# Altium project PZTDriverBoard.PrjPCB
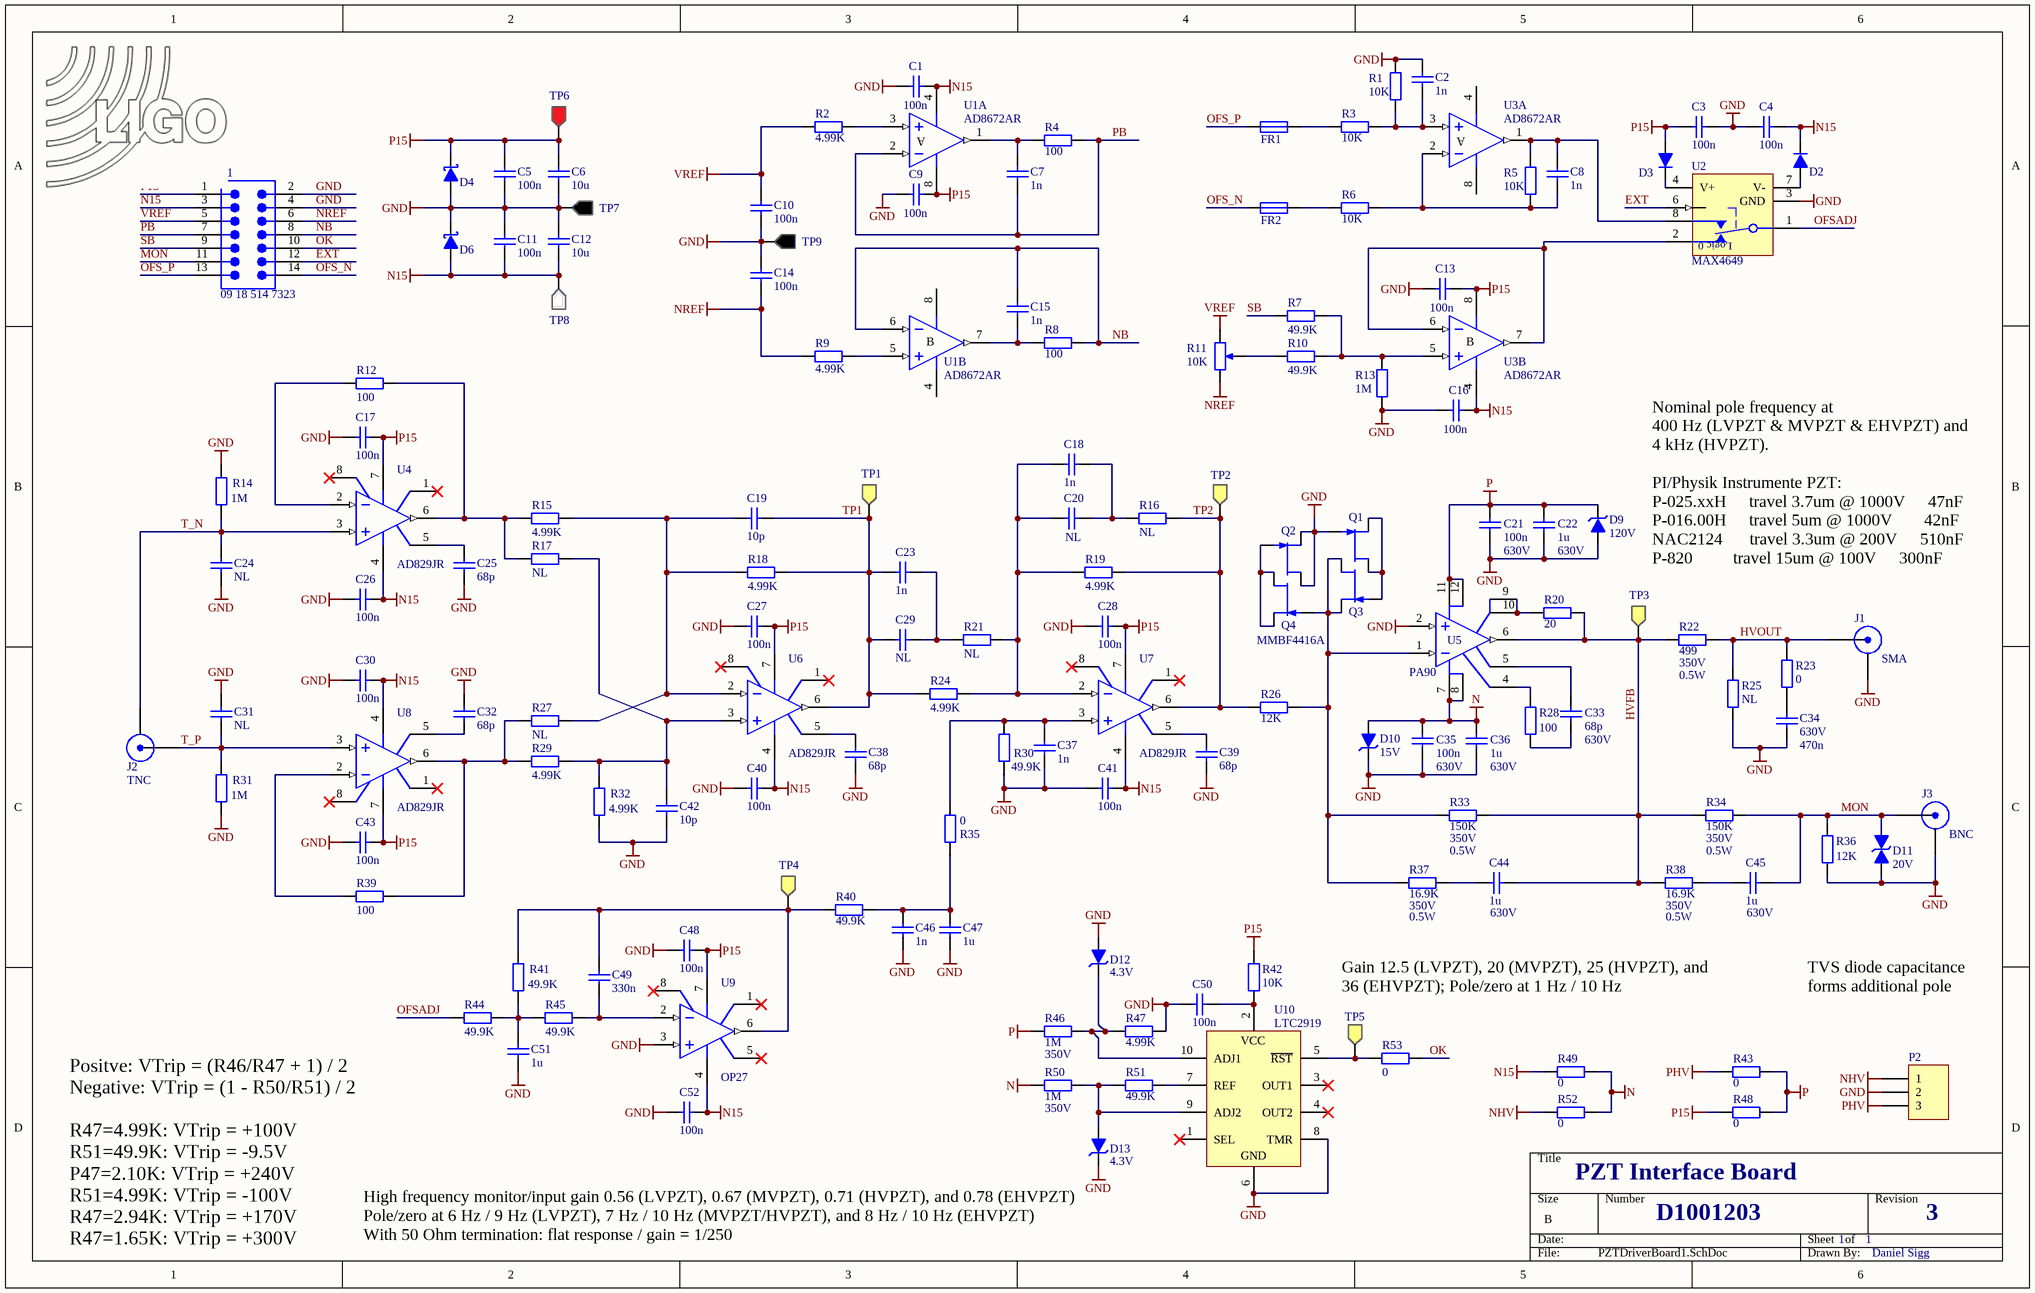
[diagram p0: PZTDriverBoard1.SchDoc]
DCC: D1001203; REV: 3
1 sheet, 146 parts. Net scope: global (net labels, ports and power ports of the same name join across sheets).
Board file: PZTDriverBoard.PcbDoc

## Sheet PZTDriverBoard1.SchDoc: =DCC
size B; Engineer: Daniel Sigg; Revision: 3; PageSetup: Record=PageOptions¦CenterHorizontal=True¦CenterVertical=True¦PrintScale=1.12¦XCorrection=1.00¦YCorrection=1.00¦PrintKind=0¦BorderSize=5000000¦LeftOffset=0¦BottomOffset=0¦Orientation=2¦PaperLength=1000¦PaperWidth=1000¦Scale=100¦PaperSource=7¦PrintQuality=-3¦MediaType=1¦DitherType=10¦PrintScaleMode=1¦PaperKind=11 x 17¦PaperIndex=121

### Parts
C1  100n  [CC2013-0805]
C2  1n  [CC2013-0805]
C3  100n  [CC2013-0805]
C4  100n  [CC2013-0805]
C5  100n  [CC3216-1206]
C6  10u  [CC3216-1206]
C7  1n  [CC2013-0805]
C8  1n  [CC2013-0805]
C9  100n  [CC2013-0805]
C10  100n  [CC3216-1206]
C11  100n  [CC3216-1206]
C12  10u  [CC3216-1206]
C13  100n  [CC2013-0805]
C14  100n  [CC3216-1206]
C15  1n  [CC2013-0805]
C16  100n  [CC2013-0805]
C17  100n  [CC2013-0805]
C18  1n  [CC2013-0805]
C19  10p  [CC2013-0805]
C20  NL  [CA-ALL8]
C21  Voltage Rating: 630V  [CL4532-1812]  (hidden comment: 100n)
C22  Voltage Rating: 630V  [CC5664-2225]  (hidden comment: 1u)
C23  1n  [CC2013-0805]
C24  NL  [CC2013-0805]
C25  68p  [CC2013-0805]
C26  100n  [CC2013-0805]
C27  100n  [CC2013-0805]
C28  100n  [CC2013-0805]
C29  NL  [CA-ALL6]
C30  100n  [CC2013-0805]
C31  NL  [CC2013-0805]
C32  68p  [CC2013-0805]
C33  Voltage Rating: 630V  [CC3216-1206]  (hidden comment: 68p)
C34  Voltage Rating: 630V  [CA-ALL5]  (hidden comment: 470n)
C35  Voltage Rating: 630V  [CL4532-1812]  (hidden comment: 100n)
C36  Voltage Rating: 630V  [CC5664-2225]  (hidden comment: 1u)
C37  1n  [CC2013-0805]
C38  68p  [CC2013-0805]
C39  68p  [CC2013-0805]
C40  100n  [CC2013-0805]
C41  100n  [CC2013-0805]
C42  10p  [CC2013-0805]
C43  100n  [CC2013-0805]
C44  Voltage Rating: 630V  [CA-ALL9]  (hidden comment: 1u)
C45  Voltage Rating: 630V  [CA-ALL9]  (hidden comment: 1u)
C46  1n  [CC2013-0805]
C47  1u  [CA-ALL2]
C48  100n  [CC2013-0805]
C49  330n  [CA-ALL2]
C50  100n  [CC2013-0805]
C51  1u  [CA-ALL2]
C52  100n  [CC2013-0805]
D2  DIODE  [DO-SOD123]  (value not drawn)
D3  DIODE  [DO-SOD123]  (value not drawn)
D4  shottky diode  [DO-SMA]  (value not drawn)
D6  shottky diode  [DO-SMA]  (value not drawn)
D9  Voltage Rating: 120V  [DO-SMB]  (hidden comment: zener diode)
D10  Voltage Rating: 15V  [DO-SMB]  (hidden comment: zener diode)
D11  Voltage Rating: 20V  [DO-SMA]  (hidden comment: zener diode)
D12  Voltage Rating: 4.3V  [SO-G3/C2.25]  (hidden comment: Zener diode)
D13  Voltage Rating: 4.3V  [SO-G3/C2.25]  (hidden comment: Zener diode)
DD00  zener diode  [DO-SMB]  (value not drawn)  (graphical)
FR1  MPZ1608D300B  [CL2013-0805]  (value not drawn)
FR2  MPZ1608D300B  [CL2013-0805]  (value not drawn)
J1  SMA  [SMA-RA]
J2  TNC  [BNC_SMA]
J3  BNC  [BNC_SMA]
LOGO1  LIGO logo  [LIGO_LOGO]  (value not drawn)  (no BOM)
P1  09 18 514 7323  [918514x323]
P2  TBlock_5.08_3  [TBLOCK-5.08-3]  (value not drawn)
Q1  MMBF4416A  [SO-G3/C2.25]  (value not drawn)
Q2  MMBF4416A  [SO-G3/C2.25]  (value not drawn)
Q3  MMBF4416A  [SO-G3/C2.25]  (value not drawn)
Q4  MMBF4416A  [SO-G3/C2.25]
R1  10K  [CR2012-0805]
R2  4.99K  [CR2012-0805]
R3  10K  [CR2012-0805]
R4  100  [CR2012-0805]
R5  10K  [CR2012-0805]
R6  10K  [CR2012-0805]
R7  49.9K  [CR2012-0805]
R8  100  [CR2012-0805]
R9  4.99K  [CR2012-0805]
R10  49.9K  [CR2012-0805]
R11  10K  [HDR1X3]
R12  100  [CR2012-0805]
R13  1M  [CR2012-0805]
R14  1M  [CR2012-0805]
R15  4.99K  [CR2012-0805]
R16  NL  [CR2012-0805]
R17  NL  [CR2012-0805]
R18  4.99K  [CR2012-0805]
R19  4.99K  [CR2012-0805]
R20  20  [CR3216-1206]
R21  NL  [CR2012-0805]
R22  Voltage Rating: 350V  Power Rating: 0.5W  [AXIAL-0.6]  (hidden comment: 499)
R23  0  [AXIAL-0.6]
R24  4.99K  [CR2012-0805]
R25  NL  [AXIAL-0.6]
R26  12K  [CR2012-0805]
R27  NL  [CR2012-0805]
R28  100  [CR3216-1206]
R29  4.99K  [CR2012-0805]
R30  49.9K  [CR2012-0805]
R31  1M  [CR2012-0805]
R32  4.99K  [CR2012-0805]
R33  Voltage Rating: 350V  Power Rating: 0.5W  [AXIAL-0.6]  (hidden comment: 150K)
R34  Voltage Rating: 350V  Power Rating: 0.5W  [AXIAL-0.6]  (hidden comment: 150K)
R35  0  [CR2012-0805]
R36  12K  [CR2012-0805]
R37  Voltage Rating: 350V  Power Rating: 0.5W  [AXIAL-0.6]  (hidden comment: 16.9K)
R38  Voltage Rating: 350V  Power Rating: 0.5W  [AXIAL-0.6]  (hidden comment: 16.9K)
R39  100  [CR2012-0805]
R40  49.9K  [CR2012-0805]
R41  49.9K  [CR2012-0805]
R42  10K  [CR2012-0805]
R43  0  [AXIAL-0.4]
R44  49.9K  [CR2012-0805]
R45  49.9K  [CR2012-0805]
R46  Voltage Rating: 350V  [AXIAL-0.6]  (hidden comment: 1M)
R47  4.99K  [CR2012-0805]
R48  0  [AXIAL-0.4]
R49  0  [AXIAL-0.4]
R50  Voltage Rating: 350V  [AXIAL-0.6]  (hidden comment: 1M)
R51  49.9K  [CR2012-0805]
R52  0  [AXIAL-0.4]
R53  0  [CR2012-0805]
TP1  Testpoint  [TP1-YLW]  (value not drawn)
TP2  Testpoint  [TP1-YLW]  (value not drawn)
TP3  Testpoint  [TP1-YLW]  (value not drawn)
TP4  Testpoint  [TP1-YLW]  (value not drawn)
TP5  Testpoint  [TP1-YLW]  (value not drawn)
TP6  Testpoint  [TP1-RED]  (value not drawn)
TP7  Testpoint  [TP1-BLK]  (value not drawn)
TP8  Testpoint  [TP1-WHT]  (value not drawn)
TP9  Testpoint  [TP1-BLK]  (value not drawn)
U1  AD8672AR  [SO-G8]  (parts A,B of 2)
U2  MAX4649  [SSO-G8/NARROW]
U3  AD8672AR  [SO-G8]  (parts A,B of 2)
U4  AD829JR  [SO-G8]
U5  PA90  [PA98]
U6  AD829JR  [SO-G8]
U7  AD829JR  [SO-G8]
U8  AD829JR  [SO-G8]
U9  OP27  [SO-G8]
U10  LTC2919  [MSOP10]

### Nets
GND: C1.1 C2.2 C3.1 C4.2 C5.1 C6.1 C9.1 C10.1 C11.1 C12.1 C13.1 C14.1 C16.1 C17.1 C21.1 C22.1 C24.1 C25.1 C26.1 C27.1 C28.1 C30.1 C31.2 C32.1 C34.1 C35.1 C36.1 C37.1 C38.1 C39.1 C40.1 C41.1 C42.1 C43.1 C46.2 C47.2 C48.1 C50.1 C51.2 C52.1 D4.1(A) D6.2(K) D9.1(A) D10.2(K) D11.1(A) D12.1(A) D13.3(K) J1.2(Y) J3.2(Y) P1.2 P1.4 P2.2 Q1.3(G) Q2.1(S) Q2.2(D) R1.2 R13.1 R14.2 R25.1 R30.2 R31.1 R32.1 R36.1 R47.1 TP7.1 TP9.1 U2.3(GND) U5.2(+IN) U9.3(IN+) U10.6(GND) U10.8(TMR)
N: C35.2 C36.2 D10.1(A) R49.2 R50.1 R52.2 U5.7(-V) U5.8(-V)
N15: C1.2 C4.1 C11.2 C12.2 C16.2 C26.2 C30.2 C40.2 C41.2 C52.2 D2.2(K) D6.1(A) P1.3 R49.1 TP8.1 U1.4(V-) U3.4(V-) U4.4(V-) U6.4(V-) U7.4(V-) U8.4(V-) U9.4(V-)
NHV: P2.1 R52.1
NREF: C14.2 P1.6 R9.1 R11.1(TOP)
P: C21.2 C22.2 D9.2(K) R43.2 R46.1 R48.2 U5.11(+V) U5.12(+V)
P15: C3.2 C5.2 C6.2 C9.2 C13.2 C17.2 C27.2 C28.2 C43.2 C48.2 D3.1(A) D4.2(K) P1.1 R42.2 R48.1 TP6.1 U1.8(V+) U3.8(V+) U4.7(V+) U6.7(V+) U7.7(V+) U8.7(V+) U9.7(V+)
PHV: P2.3 R43.1
VREF: C10.2 P1.5 R2.1 R11.2(BOT)
EXT: P1.12 U2.6(IN)
HVFB: C44.2 R20.1 R22.1 R33.2 R34.1 R38.1 TP3.1 U5.6(OUT)
HVOUT: J1.1(X) R22.2 R23.2 R25.2
MON: C45.2 D11.2(K) J3.1(X) P1.11 R34.2 R36.2
NB: C15.1 P1.8 R8.2 U1.6(IN-)
OFS_N: FR2.1 P1.14
OFS_P: FR1.1 P1.13
OFSADJ: R44.2 U2.1(COM)
OK: P1.10 R53.1
PB: C7.1 P1.7 R4.2 U1.2(IN-)
SB: P1.9 R7.2
T_N: C24.2 J2.2(Y) R14.1 U4.3(IN+)
T_P: C31.1 J2.1(X) R31.2 U8.3(IN+)
TP1: C19.1 C23.2 C29.2 R18.1 R24.2 TP1.1 U6.6(OUT)
TP2: R16.1 R19.1 R26.2 TP2.1 U7.6(OUT)
NetC2_1: C2.1 R1.1 R3.2 U3.3(IN+)
NetC7_2: C7.2 R4.1 U1.1(OUT)
NetC8_1: C8.1 R5.1 R6.2 U3.2(IN-)
NetC8_2: C8.2 R5.2 U2.8(NO) U3.1(OUT)
NetC15_2: C15.2 R8.1 U1.7(OUT)
NetC18_1: C18.1 C20.1 R19.2 R21.1 R24.1 U7.2(IN-)
NetC18_2: C18.2 C20.2 R16.2
NetC19_2: C19.2 R15.1 R18.2 R27.1 U6.2(IN-)
NetC23_1: C23.1 C29.1 R21.2
NetC25_2: C25.2 U4.5(C_COMP)
NetC32_2: C32.2 U8.5(C_COMP)
NetC33_1: C33.1 R28.1
NetC33_2: C33.2 U5.5(COMP)
NetC34_2: C34.2 R23.1
NetC37_2: C37.2 R30.1 R35.1 U7.3(IN+)
NetC38_2: C38.2 U6.5(C_COMP)
NetC39_2: C39.2 U7.5(C_COMP)
NetC42_2: C42.2 R17.1 R29.1 R32.2 U6.3(IN+)
NetC44_1: C44.1 R37.2
NetC45_1: C45.1 R38.2
NetC46_1: C46.1 C47.1 R35.2 R40.2
NetC49_1: C49.1 R40.1 R41.2 TP4.1 U9.6(OUT)
NetC49_2: C49.2 R45.1 U9.2(IN-)
NetC50_2: C50.2 R42.1 U10.2(VCC)
NetC51_1: C51.1 R41.1 R44.1 R45.2
NetD2_1: D2.1(A) U2.7(V-)
NetD3_2: D3.2(K) U2.4(V+)
NetD12_3: D12.3(K) R46.2 R47.2 U10.10(ADJ1)
NetD13_1: D13.1(A) R50.2 R51.2 U10.9(ADJ2)
NetFR1_2: FR1.2 R3.1
NetFR2_2: FR2.2 R6.1
NetQ1_1: Q1.1(S) Q1.2(D) Q3.3(G)
NetQ2_3: Q2.3(G) Q4.1(S) Q4.2(D)
NetQ3_1: Q3.1(S) Q3.2(D) Q4.3(G) R26.1 R33.1 R37.1 U5.1(-IN)
NetR2_2: R2.2 U1.3(IN+)
NetR7_1: R7.1 R10.1 R13.2 U3.5(IN+)
NetR9_2: R9.2 U1.5(IN+)
NetR10_2: R10.2 R11.3(TAP)
NetR12_1: R12.1 R15.2 R17.2 U4.6(OUT)
NetR12_2: R12.2 U4.2(IN-)
NetR20_2: R20.2 U5.9(CL) U5.10(CL)
NetR27_2: R27.2 R29.2 R39.1 U8.6(OUT)
NetR28_2: R28.2 U5.4(COMP)
NetR39_2: R39.2 U8.2(IN-)
NetR51_1: R51.1 U10.7(REF)
NetR53_2: R53.2 TP5.1 U10.5(~{RST})
NetU2_2: U2.2(NC) U3.6(IN-) U3.7(OUT)

Not connected (* = marked no-connect by the designer): D12 2; D13 2; DD00 1(A) 2(K); U2 5(N.C.); U4 1(OS_NUL)* 8(OS_NUL)*; U5 3(IQ); U6 1(OS_NUL)* 8(OS_NUL)*; U7 1(OS_NUL)* 8(OS_NUL)*; U8 1(OS_NUL)* 8(OS_NUL)*; U9 1(OS_NUL)* 5(C_COMP)* 8(OS_NUL)*; U10 1(SEL)* 3(OUT1)* 4(OUT2)*

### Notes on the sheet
- Nominal pole frequency at
  400 Hz (LVPZT & MVPZT & EHVPZT) and
  4 kHz (HVPZT).
  PI/Physik Instrumente PZT:
  P-025.xxH     travel 3.7um @ 1000V     47nF
  P-016.00H     travel 5um @ 1000V       42nF
  NAC2124      travel 3.3um @ 200V     510nF
  P-820	        travel 15um @ 100V     300nF
- Gain 12.5 (LVPZT), 20 (MVPZT), 25 (HVPZT), and
  36 (EHVPZT); Pole/zero at 1 Hz / 10 Hz
- TVS diode capacitance
  forms additional pole
- PZT Interface Board
- D1001203
- 1
- 3
- Positve: VTrip = (R46/R47 + 1) / 2
  Negative: VTrip = (1 - R50/R51) / 2
  R47=4.99K: VTrip = +100V
  R51=49.9K: VTrip = -9.5V
  P47=2.10K: VTrip = +240V
  R51=4.99K: VTrip = -100V
  R47=2.94K: VTrip = +170V
  R47=1.65K: VTrip = +300V
- (near D13) High frequency monitor/input gain 0.56 (LVPZT), 0.67 (MVPZT), 0.71 (HVPZT), and 0.78 (EHVPZT)
  Pole/zero at 6 Hz / 9 Hz (LVPZT), 7 Hz / 10 Hz (MVPZT/HVPZT), and 8 Hz / 10 Hz (EHVPZT)
  With 50 Ohm termination: flat response / gain = 1/250
- Daniel Sigg

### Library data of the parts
C1 C3 C4 C9 C13 C16 C17 C26-C28 C30 C40 C41 C43 C48 C50 C52 = ChipCap: Capacitor, surface mount; Part Number: 311-1140-1-ND; Tolerance: 10%
C2 C7 C8 C15 C18 C23 C37 C46 = ChipCap: Capacitor, surface mount; Part Number: 399-C0805C102J5GACTUCT-ND; Tolerance: 10%
C5 C10 C11 C14 = ChipCap: Capacitor, surface mount; Part Number: 311-1179-1-ND; Tolerance: 10%
C6 C12 = ChipCap: Capacitor, surface mount; Part Number: 1276-6767-1-ND; Tolerance: 10%
C19 C42 = ChipCap: Capacitor, surface mount; Part Number: 311-1099-1-ND; Tolerance: 10%
C20 C29 = CapFilmAxial: Film Capacitor, axial lead; Tolerance: 1%; Voltage Rating: 50V
C21 C35 = ChipCap: Capacitor, surface mount; Part Number: 490-16695-1-ND; Tolerance: 10%
C22 C36 = ChipCap: Capacitor, surface mount; Part Number: 490-GRM43DR7LV224KW01LCT-ND; Tolerance: 10%
C24 C31 = ChipCap: Capacitor, surface mount; Tolerance: 10%
C25 C32 C38 C39 = ChipCap: Capacitor, surface mount; Part Number: 311-1109-1-ND; Tolerance: 10%
C33 = ChipCap: Capacitor, surface mount; Part Number: 490-4300-1-ND; Tolerance: 10%
C34 = CapFilmAxial: Film Capacitor, axial lead; Part Number: P12249-ND; Tolerance: 5%
C44 C45 = CapFilmAxial: Film Capacitor, axial lead; Part Number: P12257-ND; Tolerance: 1%
C47 C51 = CapFilmAxial: Film Capacitor, axial lead; Part Number: MU12B105F; Tolerance: 1%; Voltage Rating: 50V
C49 = CapFilmAxial: Film Capacitor, axial lead; Part Number: MU12B334F; Tolerance: 1%; Voltage Rating: 50V
D2 D3 = DIODE: Single diode; Part Number: B0530W-FDICT-ND; Voltage Rating: 30V
D4 D6 = DIODE_SHOTTKY: Single shottky diode; Part Number: 641-1702-1-ND; Voltage Rating: 40V
D9 = DIODE_ZENER: Single zener diode; Part Number: SMBJ120ALFCT-ND
D10 = DIODE_ZENER: Single zener diode; Part Number: SMBJ15AFSCT-ND
D11 = DIODE_ZENER: TVS; Part Number: 576-SMAJ20CA
D12 D13 = DIODE_ZENER_SOT23: Single zener diode in SOT23 package; Part Number: MMBZ5229BLT1GOSCT-ND
DD00 = DIODE_ZENER: TVS; Part Number: SMBJ15CAFSCT-ND; Voltage Rating: 200V
FR1 FR2 = BLM31PG121SN1: ferrite bead, 20Ohm at 1GHz, 603; Part Number: 490-1041-1-ND
J1 = SMA: SMA, PCB Mount, Right Angle; Part Number: ARF1206-ND
J2 = BNC: BNC, PCB Mount, Right Angle; Part Number: WM9356-ND
J3 = BNC: BNC, PCB Mount, Right Angle; Part Number: A32258-ND
LOGO1 = LIGO_logo
P1 = 09 18 514 7323: Flat Cable Connector (IDC), Low-Profile Male Header, Angled Solder Pin, 14 Contacts, Performance Level 3; Part Number: A31177-ND
P2 = TBlock_5.08_3: Terminal block, 5.08mm, 3-Pin; Part Number: 1148070000-ND
Q1-Q4 = PMBF4416A: N-channel Silicon Junction Field-effect Transistor; Part Number: 512-MMBF4416A
R1 R3 R5 R6 R42 = ChipRes1: Resistor, surface mount; Part Number: P10KDACT-ND; Tolerance: 0.1%
R2 R9 R15 R18 R19 R24 R29 R32 R47 = ChipRes1: Resistor, surface mount; Part Number: P4.99KDACT-ND; Tolerance: 0.1%
R4 R8 R12 R39 = ChipRes1: Resistor, surface mount; Part Number: P100DACT-ND; Tolerance: 0.1%
R7 R10 R30 R40 R41 R44 R45 R51 = ChipRes1: Resistor, surface mount; Part Number: P49.9KDACT-ND; Tolerance: 0.1%
R11 = RPot2: Potentiometer; pin to pad: 2>3 3>2; Part Number: 118-3296W-1-103ALFCT-ND
R13 R14 R31 = ChipRes1: Resistor, surface mount; Part Number: P1MDACT-ND; Tolerance: 0.1%
R16 R17 R21 R27 = ChipRes1: Resistor, surface mount; Tolerance: 0.1%
R20 = ChipRes1: Resistor, surface mount; Part Number: 311-20.0FRCT-ND; Tolerance: 1%
R22 = Res2: Resistor; Part Number: PPC499ZCT-ND; Tolerance: 1%
R23 = Res2: Resistor; Part Number: JW60ZT0R00CT-ND; Tolerance: 1%; Voltage Rating: 350V; Power Rating: 0.5W
R25 = Res2: Resistor; Part Number: PPC499ZCT-ND; Tolerance: 1%; Voltage Rating: 350V; Power Rating: 0.5W
R26 R36 = ChipRes1: Resistor, surface mount; Part Number: P12KDACT-ND; Tolerance: 0.5%
R28 = ChipRes1: Resistor, surface mount; Part Number: 311-100FRCT-ND; Tolerance: 1%
R33 R34 = Res2: Resistor; Part Number: PPC150KZCT-ND; Tolerance: 1%
R35 R53 = ChipRes1: Resistor, surface mount; Part Number: 541-0.0ACT-ND; Tolerance: 0.1%
R37 R38 = Res2: Resistor; Part Number: BC4018CT-ND; Tolerance: 1%
R43 R48 R49 R52 = Res2: Resistor; Part Number: JW60ZT0R00CT-ND
R46 R50 = Res2: Resistor; Part Number: PPCQF1.0MCT-ND; Tolerance: 1%; Power Rating: 0.25W
TP1-TP5 = TP_SIGNAL: Testpoint, yellow; Part Number: 36-5009-ND
TP6 = TP_POSITIVE: Testpoint, red; Part Number: 36-5005-ND
TP7 TP9 = TP_GND: Testpoint, black; Part Number: 36-5006-ND
TP8 = TP_NEGATIVE: Testpoint, white; Part Number: 36-5007-ND
U1 U3 = OP285GS: Dual, 9MHz Precision Operational Amplifier; Part Number: 505-AD8672ARZ-REELCT-ND
U2 = MAX4649: Single SPDT analog switch; Part Number: MAX4649EKA+TCT-ND
U4 U6-U8 = AD829JR: High-Speed, Low-Noise Video Operational Amplifier; Part Number: 505-AD829ARZ-REELCT-ND
U5 = PA98: Socket 12 pin for HV Power Op Amp; Part Number: ED4864-12-ND
U9 = AD829JR: High-Speed, Low-Noise Video Operational Amplifier; Part Number: OP27GSZ-REEL7CT-ND
U10 = LTC2919: Precision Triple/Dual Input UV, OV and Negative Voltage Monitor; Part Number: LTC2919CMS-5#PBF-ND

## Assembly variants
LVPZT: not fitted C20 C24 C29 C31 R11 R16 R17 R21 R25 R27 R48 R52
HVPZT: not fitted C20 C24 C29 C31 R11 R16 R17 R21 R25 R27 R48 R49
MVPZT: not fitted C20 C24 C29 C31 R11 R16 R17 R21 R25 R27 R48 R52
EHVPZT: not fitted C20 C24 C29 C31 R11 R16 R17 R21 R25 R27 R48 R52; alternate parts J2 -> BNC_SMA_VARIANT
